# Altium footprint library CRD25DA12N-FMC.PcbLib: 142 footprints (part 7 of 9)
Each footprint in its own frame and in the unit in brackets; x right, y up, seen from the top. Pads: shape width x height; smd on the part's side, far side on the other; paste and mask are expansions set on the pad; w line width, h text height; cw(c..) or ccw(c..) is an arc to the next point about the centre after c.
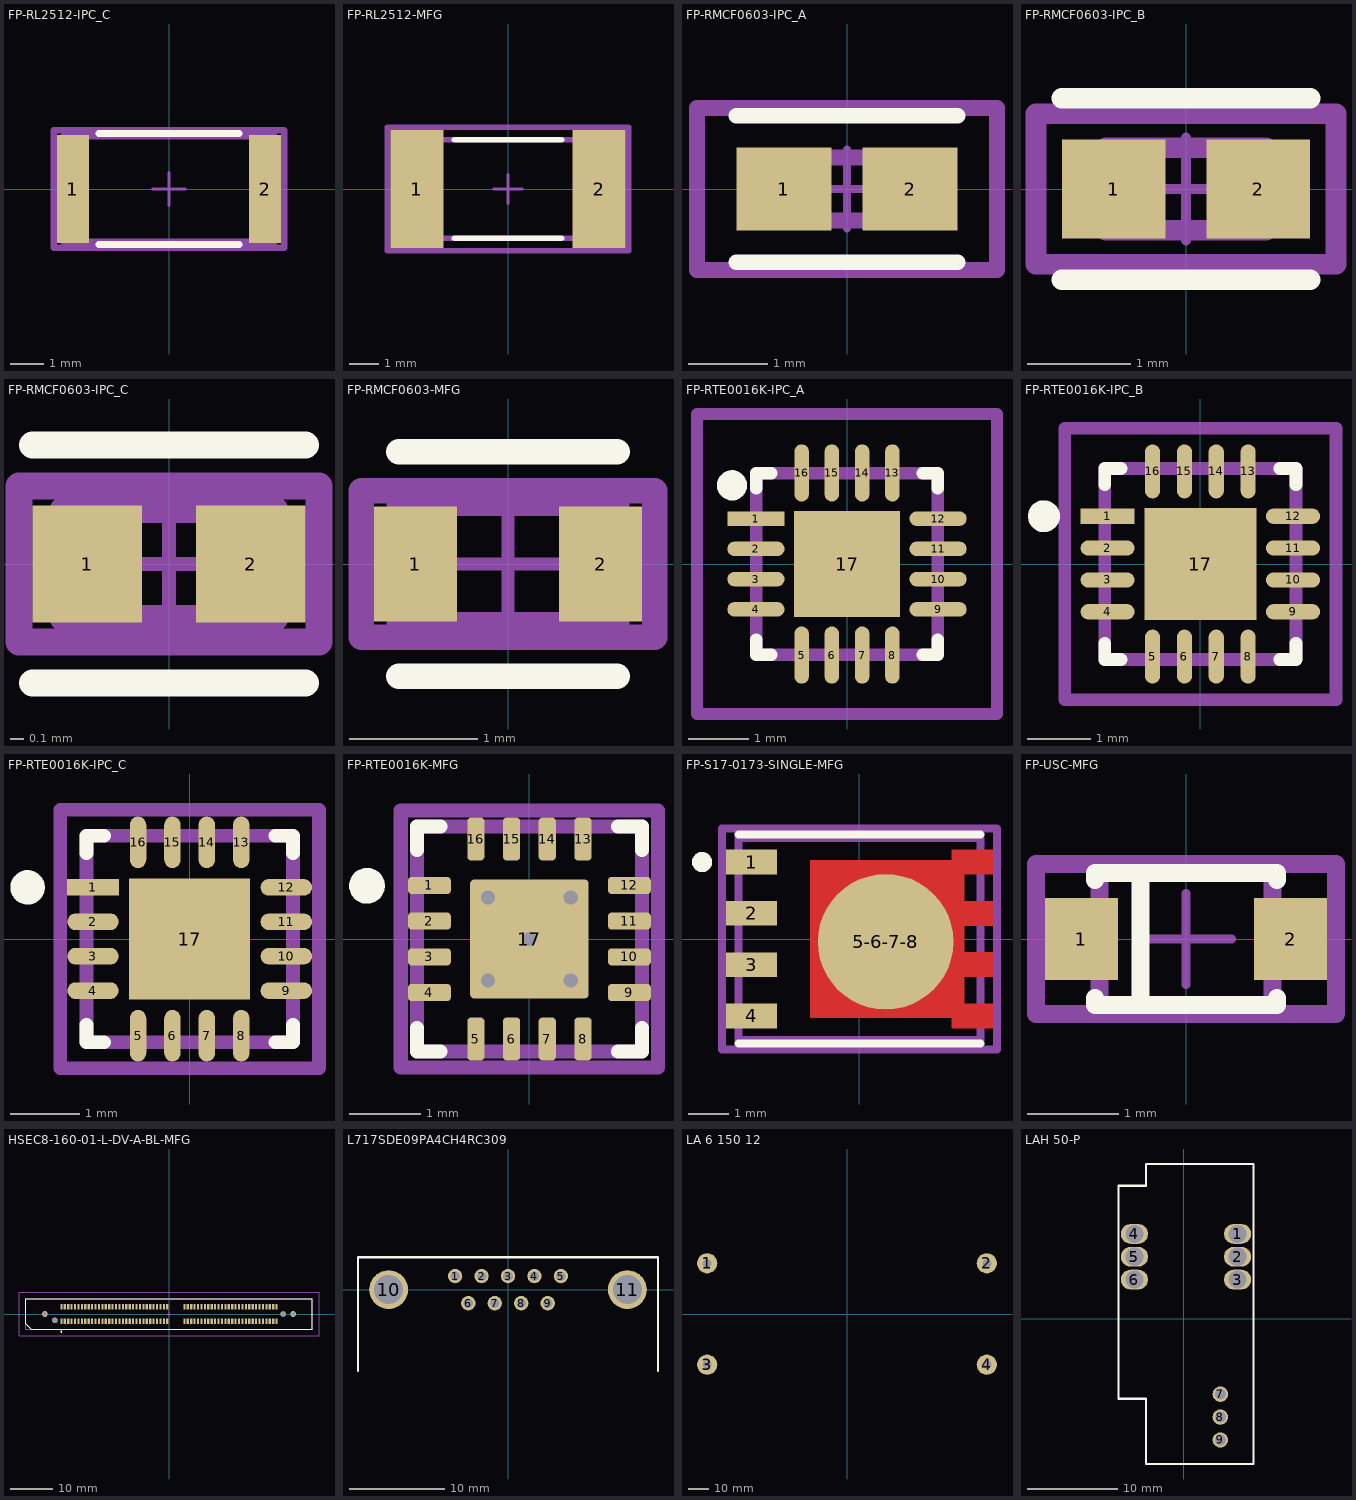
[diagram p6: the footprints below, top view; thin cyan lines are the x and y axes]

## FP-RL2512-IPC_C [mm]
pads (2):
  rect 0.958x3.258 smd paste+0 mask+0: 1(-2.902,0) 2(2.902,0)
Top Overlay:
  lines w0.2: -2.123,-1.675 2.123,-1.675 ; -2.123,1.675 2.123,1.675
Mechanical 5:
  lines w0.2: -3.481,-1.775 3.481,-1.775 3.481,1.775 -3.481,1.775 -3.481,-1.775
  text ".Designator" at 0,0.188 h1
Mechanical 13:
  lines w0.2: -3.175,-1.6 3.175,-1.6 3.175,1.6 -3.175,1.6 -3.175,-1.6
Mechanical 15:
  lines w0.2: -3.481,-1.775 3.481,-1.775 3.481,1.775 -3.481,1.775 -3.481,-1.775
Mechanical 16:
  lines w0.1: -0.5,0 0.5,0 ; 0,-0.5 0,0.5
3D body "Res_YAGEO_RL2512FK-070R1L_eec.STEP": height 0.25, standoff 0, extent -3.481,-1.775 3.481,1.775

## FP-RL2512-MFG [mm]
pads (2):
  rect 1.8x4 smd paste+0 mask+0: 1(-3.1,0) 2(3.1,0)
Top Overlay:
  lines w0.2: -1.825,-1.675 1.825,-1.675 ; -1.825,1.675 1.825,1.675
Mechanical 5:
  lines w0.2: -4.1,-2.1 4.1,-2.1 4.1,2.1 -4.1,2.1 -4.1,-2.1
  text ".Designator" at 0,0.188 h1
Mechanical 13:
  lines w0.2: -3.225,-1.675 3.225,-1.675 3.225,1.675 -3.225,1.675 -3.225,-1.675
Mechanical 15:
  lines w0.2: -4.1,-2.1 4.1,-2.1 4.1,2.1 -4.1,2.1 -4.1,-2.1
Mechanical 16:
  lines w0.1: -0.5,0 0.5,0 ; 0,-0.5 0,0.5
3D body "Res_YAGEO_RL2512FK-070R1L_eec.STEP": height 0.25, standoff 0, extent -4.1,-2.1 4.1,2.1

## FP-RMCF0603-IPC_A [mm]
pads (2):
  rect 1.206x1.058 smd paste+0 mask+0: 1(-0.801,0) 2(0.801,0)
Top Overlay:
  lines w0.2: -1.404,-0.929 1.404,-0.929 ; -1.404,0.929 1.404,0.929
Mechanical 5:
  lines w0.2: -1.904,-1.029 1.904,-1.029 1.904,1.029 -1.904,1.029 -1.904,-1.029
  text ".Designator" at 0,0.188 h1
Mechanical 13:
  lines w0.2: -0.775,-0.4 0.775,-0.4 0.775,0.4 -0.775,0.4 -0.775,-0.4
Mechanical 15:
  lines w0.2: -1.904,-1.029 1.904,-1.029 1.904,1.029 -1.904,1.029 -1.904,-1.029
Mechanical 16:
  lines w0.1: -0.5,0 0.5,0 ; 0,-0.5 0,0.5
3D body "Res_Stackpole_Electronics_RMCF0603JT1M80_eec.STEP": height 0.25, standoff 0, extent -1.904,-1.029 1.904,1.029

## FP-RMCF0603-IPC_B [mm]
pads (2):
  rect 1.006x0.958 smd paste+0 mask+0: 1(-0.701,0) 2(0.701,0)
Top Overlay:
  lines w0.2: -1.204,-0.879 1.204,-0.879 ; -1.204,0.879 1.204,0.879
Mechanical 5:
  lines w0.2: -1.454,-0.729 1.454,-0.729 1.454,0.729 -1.454,0.729 -1.454,-0.729
  text ".Designator" at 0,0.188 h1
Mechanical 13:
  lines w0.2: -0.775,-0.4 0.775,-0.4 0.775,0.4 -0.775,0.4 -0.775,-0.4
Mechanical 15:
  lines w0.2: -1.454,-0.729 1.454,-0.729 1.454,0.729 -1.454,0.729 -1.454,-0.729
Mechanical 16:
  lines w0.1: -0.5,0 0.5,0 ; 0,-0.5 0,0.5
3D body "Res_Stackpole_Electronics_RMCF0603JT1M80_eec.STEP": height 0.25, standoff 0, extent -1.454,-0.729 1.454,0.729

## FP-RMCF0603-IPC_C [mm]
pads (2):
  rect 0.806x0.858 smd paste+0 mask+0: 1(-0.601,0) 2(0.601,0)
Top Overlay:
  lines w0.2: -1.004,-0.875 1.004,-0.875 ; -1.004,0.875 1.004,0.875
Mechanical 5:
  lines w0.2: -1.104,-0.575 1.104,-0.575 1.104,0.575 -1.104,0.575 -1.104,-0.575
  text ".Designator" at 0,0.188 h1
Mechanical 13:
  lines w0.2: -0.775,-0.4 0.775,-0.4 0.775,0.4 -0.775,0.4 -0.775,-0.4
Mechanical 15:
  lines w0.2: -1.104,-0.575 1.104,-0.575 1.104,0.575 -1.104,0.575 -1.104,-0.575
Mechanical 16:
  lines w0.1: -0.5,0 0.5,0 ; 0,-0.5 0,0.5
3D body "Res_Stackpole_Electronics_RMCF0603JT1M80_eec.STEP": height 0.25, standoff 0, extent -1.104,-0.575 1.104,0.575

## FP-RMCF0603-MFG [mm]
pads (2):
  rect 0.65x0.9 smd paste+0 mask+0: 1(-0.725,0) 2(0.725,0)
Top Overlay:
  lines w0.2: -0.854,-0.879 0.854,-0.879 ; -0.854,0.879 0.854,0.879
Mechanical 5:
  lines w0.2: -1.15,-0.575 -1.15,0.575 1.15,0.575 1.15,-0.575 -1.15,-0.575
  text ".Designator" at 0,0.188 h1
Mechanical 13:
  lines w0.2: -0.85,-0.475 -0.85,0.475 0.85,0.475 0.85,-0.475 -0.85,-0.475
Mechanical 15:
  lines w0.2: -1.15,-0.575 -1.15,0.575 1.15,0.575 1.15,-0.575 -1.15,-0.575
Mechanical 16:
  lines w0.1: -0.5,0 0.5,0 ; 0,-0.5 0,0.5
3D body "Res_Stackpole_Electronics_RMCF0603JT1M80_eec.STEP": height 0.25, standoff 0, extent -1.15,-0.575 1.15,0.575

## FP-RTE0016K-IPC_A [mm]
pads (17):
  rect 0.949x0.239 smd paste+0 mask+0: 1(-1.505,0.75)
  rrect100% 0.949x0.239 smd paste+0 mask+0: 2(-1.505,0.25) 3(-1.505,-0.25) 4(-1.505,-0.75) 9(1.505,-0.75) 10(1.505,-0.25) 11(1.505,0.25) 12(1.505,0.75)
  rrect100% 0.239x0.949 smd paste+0 mask+0: 5(-0.75,-1.505) 6(-0.25,-1.505) 7(0.25,-1.505) 8(0.75,-1.505) 13(0.75,1.505) 14(0.25,1.505) 15(-0.25,1.505) 16(-0.75,1.505)
  rect 1.76x1.76 smd paste-1000 mask+0: 17(0,0)
Top Overlay:
  circle w0.25: c-1.9,1.3 r0.125
  lines w0.2: -1.5,-1.245 -1.5,-1.5 -1.245,-1.5 ; -1.5,1.245 -1.5,1.5 -1.245,1.5 ; 1.245,-1.5 1.5,-1.5 1.5,-1.245 ; 1.245,1.5 1.5,1.5 1.5,1.245
Top Paste:
  rectangle: -0.557,-0.557 0.557,0.557
Mechanical 5:
  lines w0.2: -2.479,-2.479 2.479,-2.479 2.479,2.479 -2.479,2.479 -2.479,-2.479
  text ".Designator" at 0,0.188 h1
Mechanical 13:
  lines w0.2: -1.5,-1.5 1.5,-1.5 1.5,1.5 -1.5,1.5 -1.5,-1.5
Mechanical 15:
  lines w0.2: -2.479,-2.479 2.479,-2.479 2.479,2.479 -2.479,2.479 -2.479,-2.479
Mechanical 16:
  lines w0.1: -0.5,0 0.5,0 ; 0,-0.5 0,0.5
3D body "IC_Texas_Instruments_LM51571QRTERQ1_eec.STEP": height 0.25, standoff 0, extent -2.479,-2.479 2.479,2.479

## FP-RTE0016K-IPC_B [mm]
pads (17):
  rect 0.849x0.239 smd paste+0 mask+0: 1(-1.455,0.75)
  rrect100% 0.849x0.239 smd paste+0 mask+0: 2(-1.455,0.25) 3(-1.455,-0.25) 4(-1.455,-0.75) 9(1.455,-0.75) 10(1.455,-0.25) 11(1.455,0.25) 12(1.455,0.75)
  rrect100% 0.239x0.849 smd paste+0 mask+0: 5(-0.75,-1.455) 6(-0.25,-1.455) 7(0.25,-1.455) 8(0.75,-1.455) 13(0.75,1.455) 14(0.25,1.455) 15(-0.25,1.455) 16(-0.75,1.455)
  rect 1.76x1.76 smd paste-1000 mask+0: 17(0,0)
Top Overlay:
  circle w0.25: c-2.454,0.75 r0.125
  lines w0.2: -1.5,-1.245 -1.5,-1.5 -1.245,-1.5 ; -1.5,1.245 -1.5,1.5 -1.245,1.5 ; 1.245,-1.5 1.5,-1.5 1.5,-1.245 ; 1.245,1.5 1.5,1.5 1.5,1.245
Top Paste:
  rectangle: -0.557,-0.557 0.557,0.557
Mechanical 5:
  lines w0.2: -2.129,-2.129 2.129,-2.129 2.129,2.129 -2.129,2.129 -2.129,-2.129
  text ".Designator" at 0,0.188 h1
Mechanical 13:
  lines w0.2: -1.5,-1.5 1.5,-1.5 1.5,1.5 -1.5,1.5 -1.5,-1.5
Mechanical 15:
  lines w0.2: -2.129,-2.129 2.129,-2.129 2.129,2.129 -2.129,2.129 -2.129,-2.129
Mechanical 16:
  lines w0.1: -0.5,0 0.5,0 ; 0,-0.5 0,0.5
3D body "IC_Texas_Instruments_LM51571QRTERQ1_eec.STEP": height 0.25, standoff 0, extent -2.129,-2.129 2.129,2.129

## FP-RTE0016K-IPC_C [mm]
pads (17):
  rect 0.749x0.239 smd paste+0 mask+0: 1(-1.405,0.75)
  rrect100% 0.749x0.239 smd paste+0 mask+0: 2(-1.405,0.25) 3(-1.405,-0.25) 4(-1.405,-0.75) 9(1.405,-0.75) 10(1.405,-0.25) 11(1.405,0.25) 12(1.405,0.75)
  rrect100% 0.239x0.749 smd paste+0 mask+0: 5(-0.75,-1.405) 6(-0.25,-1.405) 7(0.25,-1.405) 8(0.75,-1.405) 13(0.75,1.405) 14(0.25,1.405) 15(-0.25,1.405) 16(-0.75,1.405)
  rect 1.76x1.76 smd paste-1000 mask+0: 17(0,0)
Top Overlay:
  circle w0.25: c-2.354,0.75 r0.125
  lines w0.2: -1.5,-1.245 -1.5,-1.5 -1.245,-1.5 ; -1.5,1.245 -1.5,1.5 -1.245,1.5 ; 1.245,-1.5 1.5,-1.5 1.5,-1.245 ; 1.245,1.5 1.5,1.5 1.5,1.245
Top Paste:
  rectangle: -0.557,-0.557 0.557,0.557
Mechanical 5:
  lines w0.2: -1.879,-1.879 1.879,-1.879 1.879,1.879 -1.879,1.879 -1.879,-1.879
  text ".Designator" at 0,0.188 h1
Mechanical 13:
  lines w0.2: -1.5,-1.5 1.5,-1.5 1.5,1.5 -1.5,1.5 -1.5,-1.5
Mechanical 15:
  lines w0.2: -1.879,-1.879 1.879,-1.879 1.879,1.879 -1.879,1.879 -1.879,-1.879
Mechanical 16:
  lines w0.1: -0.5,0 0.5,0 ; 0,-0.5 0,0.5
3D body "IC_Texas_Instruments_LM51571QRTERQ1_eec.STEP": height 0.25, standoff 0, extent -1.879,-1.879 1.879,1.879

## FP-RTE0016K-MFG [mm]
pads (17):
  rrect42% 0.6x0.24 smd paste+0 mask+0: 1(-1.4,0.75) 2(-1.4,0.25) 3(-1.4,-0.25) 4(-1.4,-0.75) 9(1.4,-0.75) 10(1.4,-0.25) 11(1.4,0.25) 12(1.4,0.75)
  rrect42% 0.24x0.6 smd paste+0 mask+0: 5(-0.75,-1.4) 6(-0.25,-1.4) 7(0.25,-1.4) 8(0.75,-1.4) 13(0.75,1.4) 14(0.25,1.4) 15(-0.25,1.4) 16(-0.75,1.4)
  rrect6% 1.66x1.66 smd paste-1000 mask+0: 17(0,0)
via -0.58,0.58 diameter 0.5 hole 0.2
via 0.58,0.58 diameter 0.5 hole 0.2
via 0.58,-0.58 diameter 0.5 hole 0.2
via -0.58,-0.58 diameter 0.5 hole 0.2
via 0,0 diameter 0.5 hole 0.2
Top Overlay:
  circle w0.25: c-2.275,0.745 r0.125
  lines w0.2: -1.575,-1.245 -1.575,-1.575 -1.245,-1.575 ; -1.575,1.245 -1.575,1.575 -1.245,1.575 ; 1.245,-1.575 1.575,-1.575 1.575,-1.245 ; 1.245,1.575 1.575,1.575 1.575,1.245
Top Paste:
  region: -0.705,0.755 0.705,0.755 0.715,0.755 0.733,0.747 0.747,0.733 0.755,0.715 0.755,0.705 0.755,-0.705 0.755,-0.715 0.747,-0.733 0.733,-0.747 0.715,-0.755 0.705,-0.755 -0.705,-0.755 -0.715,-0.755 -0.733,-0.747 -0.747,-0.733 -0.755,-0.715 -0.755,-0.705 -0.755,0.705 -0.755,0.715 -0.747,0.733 -0.733,0.747 -0.715,0.755
Mechanical 5:
  lines w0.2: -1.8,-1.8 1.8,-1.8 1.8,1.8 -1.8,1.8 -1.8,-1.8
  text ".Designator" at 0,0.188 h1
Mechanical 13:
  lines w0.2: -1.575,-1.575 1.575,-1.575 1.575,1.575 -1.575,1.575 -1.575,-1.575
Mechanical 15:
  lines w0.2: -1.8,-1.8 1.8,-1.8 1.8,1.8 -1.8,1.8 -1.8,-1.8
Mechanical 16:
  lines w0.1: -0.5,0 0.5,0 ; 0,-0.5 0,0.5
3D body "IC_Texas_Instruments_XLM51571QRTERQ1_eec.STEP": height 0.25, standoff 0, extent -1.8,-1.8 1.8,1.8

## FP-S17-0173-SINGLE-MFG [mm]
pads (5):
  rect 1.27x0.61 smd paste+0 mask+0: 1(-2.67,1.905) 2(-2.67,0.635) 3(-2.67,-0.635) 4(-2.67,-1.905)
  round 3.356 smd paste+0 mask+0: 5-6-7-8(0.65,-0.069)
Top Layer:
  region: -1.215,1.955 2.285,1.955 2.285,2.21 3.305,2.21 3.305,1.6 2.595,1.6 2.595,0.94 3.305,0.94 3.305,0.33 2.595,0.33 2.595,-0.33 3.305,-0.33 3.305,-0.94 2.595,-0.94 2.595,-1.6 3.305,-1.6 3.305,-2.21 2.285,-2.21 2.285,-1.955 -1.215,-1.955
Top Overlay:
  circle w0.25: c-3.895,1.905 r0.125
  lines w0.2: -2.995,-2.585 2.995,-2.585 ; -2.995,2.585 2.995,2.585
Mechanical 5:
  lines w0.2: -3.405,-2.73 3.405,-2.73 3.405,2.73 -3.405,2.73 -3.405,-2.73
  text ".Designator" at 0,0.188 h1
Mechanical 13:
  lines w0.2: -2.995,-2.5 2.995,-2.5 2.995,2.5 -2.995,2.5 -2.995,-2.5
Mechanical 15:
  lines w0.2: -3.405,-2.73 3.405,-2.73 3.405,2.73 -3.405,2.73 -3.405,-2.73
Mechanical 16:
  lines w0.1: -0.5,0 0.5,0 ; 0,-0.5 0,0.5
3D body "Trans_Vishay_SI7461DP-T1-E3_eec.STEP": height 0.25, standoff 0, extent -3.405,-2.73 3.405,2.73

## FP-USC-MFG [mm]
pads (2):
  rect 0.8x0.9 smd paste+0 mask+0: 1(-1.15,0) 2(1.15,0)
Top Overlay:
  lines w0.2: -1,-0.65 -1,-0.725 1,-0.725 1,-0.65 ; -1,0.65 -1,0.725 1,0.725 1,0.65 ; -0.5,-0.725 -0.5,0.725
Mechanical 5:
  lines w0.2: -1.65,-0.825 -1.65,0.825 1.65,0.825 1.65,-0.825 -1.65,-0.825
  text ".Designator" at 0,0 h1
Mechanical 13:
  lines w0.2: -0.95,-0.725 -0.95,0.725 0.95,0.725 0.95,-0.725 -0.95,-0.725
Mechanical 15:
  lines w0.2: -1.65,-0.825 -1.65,0.825 1.65,0.825 1.65,-0.825 -1.65,-0.825
Mechanical 16:
  lines w0.1: -0.5,0 0.5,0 ; 0,-0.5 0,0.5
3D body "Diode_Toshiba_CUS520_H3F_eec.STEP": height 0.25, standoff 0, extent -1.65,-0.825 1.65,0.825

## HSEC8-160-01-L-DV-A-BL-MFG [mm]
pads (124):
  rect 0.5x1.2 smd paste+0 mask+0: 1(-25.2,-1.7) 2(-25.2,1.7) 3(-24.4,-1.7) 4(-24.4,1.7) 5(-23.6,-1.7) 6(-23.6,1.7) 7(-22.8,-1.7) 8(-22.8,1.7) 9(-22,-1.7) 10(-22,1.7) 11(-21.2,-1.7) 12(-21.2,1.7) 13(-20.4,-1.7) 14(-20.4,1.7) 15(-19.6,-1.7) 16(-19.6,1.7) 17(-18.8,-1.7) 18(-18.8,1.7) 19(-18,-1.7) 20(-18,1.7) 21(-17.2,-1.7) 22(-17.2,1.7) 23(-16.4,-1.7) 24(-16.4,1.7) 25(-15.6,-1.7) 26(-15.6,1.7) 27(-14.8,-1.7) 28(-14.8,1.7) 29(-14,-1.7) 30(-14,1.7) 31(-13.2,-1.7) 32(-13.2,1.7) 33(-12.4,-1.7) 34(-12.4,1.7) 35(-11.6,-1.7) 36(-11.6,1.7) 37(-10.8,-1.7) 38(-10.8,1.7) 39(-10,-1.7) 40(-10,1.7) 41(-9.2,-1.7) 42(-9.2,1.7) 43(-8.4,-1.7) 44(-8.4,1.7) 45(-7.6,-1.7) 46(-7.6,1.7) 47(-6.8,-1.7) 48(-6.8,1.7) 49(-6,-1.7) 50(-6,1.7) 51(-5.2,-1.7) 52(-5.2,1.7) 53(-4.4,-1.7) 54(-4.4,1.7) 55(-3.6,-1.7) 56(-3.6,1.7) 57(-2.8,-1.7) 58(-2.8,1.7) 59(-2,-1.7) 60(-2,1.7) 61(-1.2,-1.7) 62(-1.2,1.7) 63(-0.4,-1.7) 64(-0.4,1.7) 65(3.6,-1.7) 66(3.6,1.7) 67(4.4,-1.7) 68(4.4,1.7) 69(5.2,-1.7) 70(5.2,1.7) 71(6,-1.7) 72(6,1.7) 73(6.8,-1.7) 74(6.8,1.7) 75(7.6,-1.7) 76(7.6,1.7) 77(8.4,-1.7) 78(8.4,1.7) 79(9.2,-1.7) 80(9.2,1.7) 81(10,-1.7) 82(10,1.7) 83(10.8,-1.7) 84(10.8,1.7) 85(11.6,-1.7) 86(11.6,1.7) 87(12.4,-1.7) 88(12.4,1.7) 89(13.2,-1.7) 90(13.2,1.7) 91(14,-1.7) 92(14,1.7) 93(14.8,-1.7) 94(14.8,1.7) 95(15.6,-1.7) 96(15.6,1.7) 97(16.4,-1.7) 98(16.4,1.7) 99(17.2,-1.7) 100(17.2,1.7) 101(18,-1.7) 102(18,1.7) 103(18.8,-1.7) 104(18.8,1.7) 105(19.6,-1.7) 106(19.6,1.7) 107(20.4,-1.7) 108(20.4,1.7) 109(21.2,-1.7) 110(21.2,1.7) 111(22,-1.7) 112(22,1.7) 113(22.8,-1.7) 114(22.8,1.7) 115(23.6,-1.7) 116(23.6,1.7) 117(24.4,-1.7) 118(24.4,1.7) 119(25.2,-1.7) 120(25.2,1.7)
  round 1.34 hole 0.84 paste-2539.97 mask+0: 121(-29.05,0) 122(29.05,0)
  round 1.27 hole 1.27 unplated paste-2539.97 mask+0: ""(-26.7,-1.5) ""(26.7,0)
Top Overlay:
  circle w0.25: c-25.2,-4.125 r0.125
  lines w0.2: -33.55,-2.295 -32.28,-3.565 33.55,-3.565 33.55,3.565 -33.55,3.565 -33.55,-2.295
Top Paste:
  circle w1.27: c29.05,0 r0.635
  circle w1.27: c-29.05,0 r0.635
Mechanical 5:
  lines w0.2: -35.115,-5.09 -35.115,5.09 35.115,5.09 35.115,-5.09 -35.115,-5.09
  text ".Designator" at 0,0.188 h1
Mechanical 13:
  lines w0.2: -33.55,-3.565 -33.55,3.565 33.55,3.565 33.55,-3.565 -33.55,-3.565
Mechanical 15:
  lines w0.2: -35.115,-5.09 -35.115,5.09 35.115,5.09 35.115,-5.09 -35.115,-5.09
Mechanical 16:
  lines w0.1: -0.5,0 0.5,0 ; 0,-0.5 0,0.5
3D body "Conn_Samtec_HSEC8-160-01-L-DV-A-BL_eec.STEP": height 0.25, standoff 0, extent -35.115,-5.09 35.115,5.09

## L717SDE09PA4CH4RC309 [mm] "CONN D-SUB PLUG 9POS R/A SLDR"
height 12.55
pads (11):
  round 1.508 hole 1: 1(-5.54,1.42) 2(-2.77,1.42) 3(0,1.42) 4(2.77,1.42) 5(5.54,1.42) 6(-4.155,-1.42) 7(-1.385,-1.42) 8(1.385,-1.42) 9(4.155,-1.42)
  round 4.066 hole 3.05: 10(-12.495,0) 11(12.495,0)
Top Overlay:
  lines w0.254: -15.7,-8.5 -15.7,3.4 15.7,3.4 15.7,-8.5
3D body "Amphenol L717SDE09PA4CH4RC309 Color.STEP": height 12.55, standoff -3.2, extent -15.4,-15.6 15.405,3

## LA 6 150 12 [mm]
pads (4):
  round 10 hole 4.5: 1(-69,25) 2(69,25) 3(-69,-25) 4(69,-25)
3D body "Fischer Elektronik LA 6 150 + Fan.STEP": height 86.05, standoff 0.05, extent -104.53,-31.052 74.97,30.948

## LAH 50-P [mil]
pads (9):
  oval 118.74x86.61 hole 78.74 mask+7.87: 1(235,370) 2(235,270) 3(235,170) 5(-215,270) 6(-215,170)
  oval 118.74x86.61 hole 78.74 paste-99999 mask+7.87: 4(-215,370)
  round 67.24 hole 47.24: 7(160,-330) 8(160,-430) 9(160,-530)
Top Overlay:
  lines w10: -285,-350 -285,580 -165,580 -165,675 305,675 305,-635 -165,-635 -165,-350 -285,-350
3D body "LAH 50-P_blackbox.stp": height 789.5, standoff -182.94, extent -284.07,-636.02 304.07,675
